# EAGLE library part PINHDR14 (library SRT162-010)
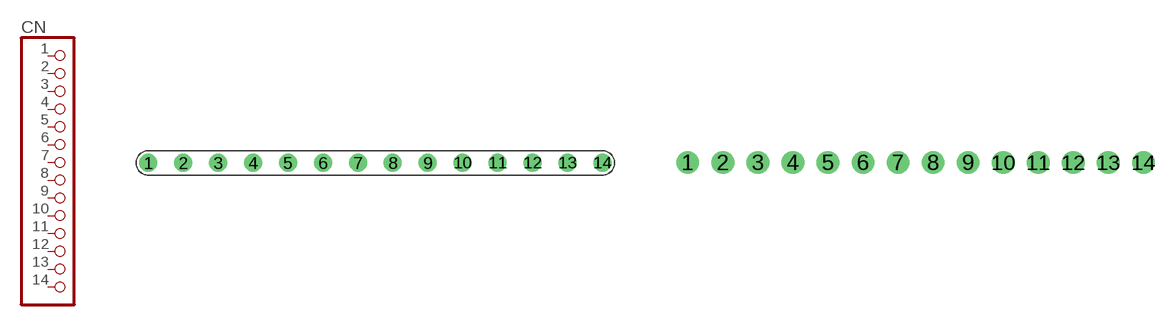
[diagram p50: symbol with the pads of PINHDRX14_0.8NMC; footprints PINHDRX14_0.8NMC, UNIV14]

Designator prefix CN

## PINHDR140.8NMC  [PINHDRX14_0.8NMC]
1  1  pas
2  2  pas
3  3  pas
4  4  pas
5  5  pas
6  6  pas
7  7  pas
8  8  pas
9  9  pas
10  10  pas
11  11  pas
12  12  pas
13  13  pas
14  14  pas

## PINHDR14U  [UNIV14]
Pads as for PINHDRX14_0.8NMC

## Footprint PINHDRX14_0.8NMC (pad centres in mm)
drill 0.8 round: 1 -16.51,0; 2 -13.97,0; 3 -11.43,0; 4 -8.89,0; 5 -6.35,0; 6 -3.81,0; 7 -1.27,0; 8 1.27,0; 9 3.81,0; 10 6.35,0; 11 8.89,0; 12 11.43,0; 13 13.97,0; 14 16.51,0

## Footprint UNIV14 (pad centres in mm)
drill 1.1 round: 1 -16.51,0; 2 -13.97,0; 3 -11.43,0; 4 -8.89,0; 5 -6.35,0; 6 -3.81,0; 7 -1.27,0; 8 1.27,0; 9 3.81,0; 10 6.35,0; 11 8.89,0; 12 11.43,0; 13 13.97,0; 14 16.51,0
